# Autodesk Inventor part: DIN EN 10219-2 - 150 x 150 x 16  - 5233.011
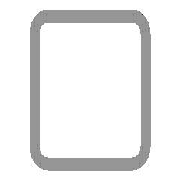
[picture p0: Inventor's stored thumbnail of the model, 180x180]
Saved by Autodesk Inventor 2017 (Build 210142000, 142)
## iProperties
Created: 2016-02
Part Number: DIN EN 10219-2 - 150 x 150 x 16  - 5233.011
Material: Steel, Mild
Description: Cold formed welded structural hollow sections of non-alloy and fine grain structural steel
Document SubType Name: Modeling
Standard: DIN
Designer: iusti
Standard Revision: 2006-07
Standards Organization: DIN
Language: en-US
Size Designation: 150 x 150 x 16
Categories: <MemberInstance><Categories><Category DisplayName="Structural Shapes" InternalName="089c4875-fa83-4c05-b084-43b9cc11f5ed" Mnemonic="GRDR"><CategoryParameter Dis
Stock Number: 150 x 150 x 16
Mass: 301820 g
Surface Area: 48238.1 cm^2
Volume: 38448.4 cm^3
Density: 7.85 g/cm^3
Appearance: Semi-Polished
IsCustomPart: 1
G_W: 150.000 mm
G_H: 150.000 mm
G_L: 5233.011 mm
+A8523F61-15A1-41A4-8D30-2D7D9D924B11+CUTDETAIL2: Cut
+987C6673-447C-412A-9B24-0CD20188E66E+CUTDETAIL3: Miter 69.88 deg
_CCFamilyMember: 76
_CCFamilyDisplayName: DIN EN 10219-2 (Square Hollow Section - Cold Formed) - Cold formed welded structural hollow sections of non-alloy and fine grain structural steel
_FrameMemberDoc: Frame Member File
_Version: 15.0.0
_GetPNFromCC: 1
Author: iusti
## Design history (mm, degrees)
node "Start plane"
node "End plane"
sketch "Sketch"
  geometry: L1 (-75, -27)-(-75, 27); L2 (-27, 75)-(27, 75); L3 (75, 27)-(75, -27); L4 (27, -75)-(-27, -75); L5 (-27, 59)-(27, 59); L6 (59, 27)-(59, -27); L7 (27, -59)-(-27, -59); L8 (-59, -27)-(-59, 27); L9 (0, 118.918)-(0, -118.918) reference; L10 (-118.918, 0)-(118.918, 0) reference; A1 r 48 centre (-27, -27) between (-75, -27) and (-27, -75); A2 r 48 centre (-27, 27) between (-27, 75) and (-75, 27); A3 r 48 centre (27, 27) between (75, 27) and (27, 75); A4 r 48 centre (27, -27) between (27, -75) and (75, -27); A5 r 32 centre (-27, 27) between (-27, 59) and (-59, 27); A6 r 32 centre (27, 27) between (59, 27) and (27, 59); A7 r 32 centre (27, -27) between (27, -59) and (59, -27); A8 r 32 centre (-27, -27) between (-59, -27) and (-27, -59)
  constraints: 16 end point, 16 point on circle, 8 centre point, 8 tangent, 4 parallel, 3 equal radius, 2 perpendicular, 7 other
  dimensions: "d7" = 48 radius of A1 (= G_IR); "d10" = 150 distance between parallel lines of L2 L4 (= G_H); "d11" = 150 distance between parallel lines of L1 L3 (= G_W); "d12" = 16 distance between parallel lines of L3 L6 (= G_T); "d15" = 75 distance between parallel lines of L2 L10 (= 0.5 x d10); "d16" = 75 distance between parallel lines of L9 L3 (= 0.5 x d11)
extrude "Body" new body sketch "Sketch" stored distance "d3" = 5233.01077 (= G_L); taper "d4" = 0 deg
node "Driven Length"
  sketch "Sketch3"
    geometry: L1 (0, 0)-(10, 0) reference
    constraints: 2 end point, 1 horizontal
  workplane "Work Plane3"
  sketch "Sketch4"
    geometry: L1 (-2, 34.78)-(12, 34.78) reference; L2 (-2, 5267.791)-(12, 5267.791) reference
    dimensions: "d18" = 5233.01077 distance between parallel lines of L1 L2 (derived)
workplane "Work Plane5"
split "Split2"
workplane "Work Plane6"
split "Split3"
body "Solid1"
other parameters: "G_W" = 150 [user parameter; used in 1 equation term], "G_H" = 150 [user parameter; used in 1 equation term], "G_T" = 16 [user parameter; used in 1 equation term], "G_IR" = 48 [user parameter; used in 1 equation term], "G_L" = 5233.01077 (= d18) [user parameter; used in 1 equation term], "G_OFFSET_START" = -34.77977 [user parameter; used in 1 equation term], "G_OFFSET_END" = 27.4779 [user parameter; used in 1 equation term], "d13" = 34.77977 (= -G_OFFSET_START), "d14" = 5267.79054 (= G_OFFSET_END + B_L), "B_L" = 5240.31264 [user parameter; used in 1 equation term], "d17" = 90 deg
